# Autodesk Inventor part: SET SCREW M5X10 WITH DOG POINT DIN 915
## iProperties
IsCustomPart: 1
Created: 2006-02
Part Number: SET SCREW M5X10 WITH DOG POINT DIN 915
Material: Steel, Mild
Description: Hexagon Socket Set Screw
Document SubType Name: Modeling
Standard: DIN 915
Designer: Andy Moles
Standards Organization: DIN
Language: en-US
Size Designation: M5 x 10
Categories: <MemberInstance><Categories><Category DisplayName="Fasteners" InternalName="e4da775c-781d-43d5-af7c-5136215cf5a6" Mnemonic="FSTN"><Category DisplayName="Bolts"
Density: 7.86 g/cm^3
Mass: 1.15986 g
Surface Area: 1.9956 cm^2
Volume: 0.147565 cm^3
Author: Andy Moles
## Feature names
1. Body [Revolution]
2. Chamfer1
3. Slot [Extrusion]
4. Chamfer2
